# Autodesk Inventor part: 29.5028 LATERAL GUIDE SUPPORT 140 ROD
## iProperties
Created: 2007-07
Part Number: 29.5028 LATERAL GUIDE SUPPORT 140 ROD
Material: Stainless Steel
Document SubType Name: Modeling
Designer: Andy Moles
Density: 8.08 g/cm^3
Author: Andy Moles
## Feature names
1. Extrusion1
2. Chamfer1
3. Extrusion2
4. Chamfer2
